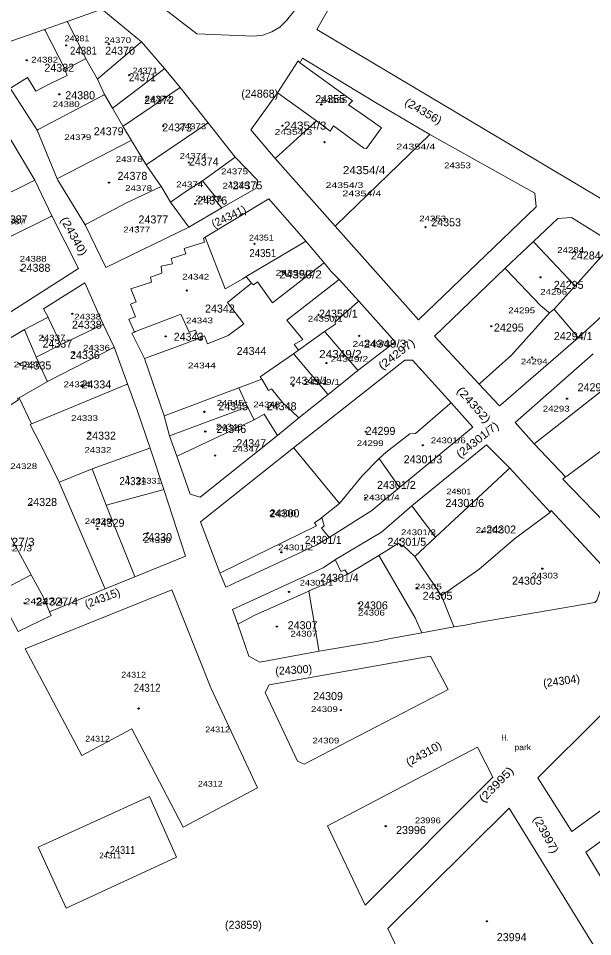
# Model space of a CAD drawing. Extents: x 649608 to 651081, y 237980 to 241202.
# Drawn here: x 650325.9 to 650584.2, y 238660.5 to 239073.7 of the extents above; entities that cross this region are included whole.
import ezdxf

# ---------------------------------------------------------------- set-up
doc = ezdxf.new("R2010")
doc.units = 0
doc.header["$PDMODE"] = 32
doc.header["$PDSIZE"] = 0.5
for name, color, linetype in [('19', 7, 'Continuous'), ('20', 7, 'Continuous'), ('6', 7, 'Continuous')]:
    doc.layers.add(name, color=color, linetype=linetype)
doc.layers.add('3', color=7, linetype='Continuous', lineweight=13)
doc.layers.add('5', color=7, linetype='Continuous', lineweight=13)

msp = doc.modelspace()

# ---------------------------------------------------------------- linework, layer by layer
at = {"layer": '3'}
for p, q in [((650333.268, 239000.784), (650309.651, 239040.458)), ((650433.511, 239000.829), (650423.374, 239011.159)), ((650333.268, 239000.784), (650340.965, 238984.736)), ((650549.32, 238891.838), (650584.458, 238922.778))]:
    msp.add_line(p, q, dxfattribs=at)
for points in [[(650634.917, 238992.051), (650633.914, 238992.9), (650730.416, 239151.667), (650574.402, 239245.255), (650564.003, 239226.917), (650562.503, 239225.238), (650535.575, 239197.674), (650472.242, 239088.563), (650471.65, 239089.049), (650460.092, 239068.577)], [(650450.824, 239078.036), (650446.42, 239072.723), (650443.555, 239069.71), (650439.954, 239067.534), (650435.893, 239066.089), (650431.679, 239065.666), (650406.177, 239066.662), (650387.929, 239080.729), (650389.909, 239083.539), (650386.225, 239086.383), (650392.442, 239094.932), (650393.624, 239097.016), (650398.749, 239100.87)], [(650381.221, 239063.049), (650363.393, 239077.851), (650347.856, 239072.254), (650337.653, 239068.717)], [(650337.653, 239068.717), (650315.85, 239061.08), (650313.77, 239056.136), (650322.253, 239042.174), (650334.272, 239023.41), (650343.346, 239001.41), (650344.344, 239002.082)], [(650634.917, 238992.051), (650623.091, 238971.671), (650460.092, 239068.577)], [(650423.374, 239011.159), (650411.304, 239026.695), (650398.664, 239042.617), (650391.687, 239051.029), (650381.221, 239063.049)], [(650510.99, 239021.351), (650486.457, 239035.738), (650453.649, 239055.761), (650452.467, 239053.677)], [(650452.467, 239053.677), (650451.809, 239054.587), (650442.408, 239040.175)], [(650442.408, 239040.175), (650430.436, 239023.514), (650441.41, 239010.562)], [(650340.965, 238984.736), (650352.967, 238961.072), (650313.65, 238936.034), (650300.262, 238964.625), (650292.437, 238980.621), (650272.393, 239018.949)], [(650510.99, 239021.351), (650558.173, 238995.05), (650558.781, 238988.827), (650505.81, 238938.013), (650468.373, 238980.177), (650441.41, 239010.562)], [(650343.346, 239001.41), (650343.65, 239000.91), (650355.883, 238980.811)], [(650417.428, 238988.393), (650432.862, 238997.289), (650433.511, 239000.829)], [(650455.189, 238973.453), (650438.513, 238992.491), (650409.892, 238975.257)], [(650355.883, 238980.811), (650365.303, 238961.605), (650402.554, 238979.756), (650417.428, 238988.393)], [(650557.608, 238973.197), (650568.5, 238983.626), (650574.654, 238984.056)], [(650574.654, 238984.056), (650593.391, 238972.409), (650612.065, 238961.343)], [(650409.892, 238975.257), (650409.196, 238974.66), (650409.619, 238973.021), (650400.498, 238970.082), (650401.26, 238967.697), (650394.687, 238965.595), (650395.169, 238963.165), (650390.138, 238962.177), (650390.479, 238959.037), (650385.279, 238957.237), (650385.814, 238954.882), (650376.54, 238951.895), (650378.853, 238946.141), (650376.276, 238945.126), (650378.513, 238939.373), (650375.557, 238938.34), (650378.121, 238932.504), (650376.872, 238932.047)], [(650470.107, 238956.158), (650466.615, 238959.822), (650463.479, 238963.693), (650455.189, 238973.453)], [(650533.153, 238909.068), (650513.076, 238930.587), (650544.868, 238961.181), (650557.608, 238973.197)], [(650542.337, 238899.294), (650542.837, 238899.726), (650577.732, 238929.883), (650612.065, 238961.343)], [(650478.527, 238915.245), (650495.37, 238928.17), (650478.959, 238946.38), (650470.107, 238956.158)], [(650339.242, 238939.231), (650337.18, 238943.014), (650355.801, 238954.65), (650364.015, 238936.01), (650369.04, 238925.679), (650375.006, 238909.155)], [(650271.291, 238897.715), (650294.729, 238912.715), (650314.262, 238925.069), (650328.6, 238933.699), (650339.242, 238939.231)], [(650403.125, 238859.534), (650397.127, 238876.638), (650393.802, 238885.779), (650391.423, 238894.805), (650382.565, 238920.602), (650376.872, 238932.047)], [(650449.671, 238880.424), (650499.784, 238919.85), (650500.06, 238919.874)], [(650500.06, 238919.874), (650503.131, 238919.892), (650520.526, 238900.585)], [(650403.125, 238859.534), (650407.586, 238858.228), (650442.453, 238885.884), (650451.993, 238893.975), (650465.186, 238904.357), (650478.527, 238915.245)], [(650375.006, 238909.155), (650379.441, 238896.85), (650385.126, 238880.246), (650391.346, 238861.707)], [(650542.337, 238899.294), (650541.867, 238899.794), (650533.153, 238909.068)], [(650520.526, 238900.585), (650530.259, 238889.734), (650497.303, 238862.53)], [(650598.293, 238837.737), (650570.749, 238866.326), (650572.041, 238867.352), (650557.942, 238882.26), (650549.32, 238891.838)], [(650502.918, 238854.251), (650536.432, 238881.789), (650546.878, 238871.199), (650565.07, 238851.397)], [(650416.54, 238824.133), (650407.867, 238847.157), (650449.671, 238880.424)], [(650391.346, 238861.707), (650401.019, 238831.658), (650378.334, 238822.368), (650364.904, 238817.003), (650339.956, 238806.625), (650340.606, 238804.956)], [(650497.303, 238862.53), (650484.876, 238852.208), (650465.698, 238840.087)], [(650468.522, 238830.107), (650489.204, 238842.525), (650502.918, 238854.251)], [(650565.07, 238851.397), (650565.558, 238852.244), (650590.075, 238825.617), (650590.507, 238824.487), (650586.122, 238811.692), (650585.113, 238810.756), (650533.547, 238801.962), (650526.843, 238800.541), (650521.843, 238799.848), (650507.309, 238797.143)], [(650465.698, 238840.087), (650459.784, 238836.683), (650419.169, 238817.784), (650416.54, 238824.133)], [(650424.676, 238801.128), (650422.174, 238807.605), (650463.019, 238826.481), (650468.522, 238830.107)], [(650340.606, 238804.956), (650325.826, 238797.694), (650318.278, 238811.853), (650316.195, 238815.232)], [(650461.18, 238788.846), (650434.533, 238783.971), (650429.494, 238786.658), (650424.676, 238801.128)], [(650507.309, 238797.143), (650493.309, 238794.621), (650487.193, 238793.233), (650461.18, 238788.846)], [(650591.619, 238681.099), (650581.197, 238698.525), (650599.518, 238711.797), (650621.459, 238728.065)]]:
    msp.add_lwpolyline(points, dxfattribs=at)
for points in [[(650394.908, 238816.572), (650328.88, 238789.988), (650354.501, 238742.001), (650376.901, 238753.911), (650400, 238709.701), (650433.501, 238727.35), (650416.523, 238763.665), (650412.488, 238772.343)], [(650644.085, 238758.04), (650574.778, 238707.779), (650559.577, 238731.881), (650614.901, 238786.963), (650625.096, 238784.845)], [(650519.178, 238771.662), (650454.432, 238738.081), (650451.428, 238739.381), (650436.94, 238770.253), (650438.637, 238773.831), (650511.211, 238786.723)], [(650481.944, 238674.679), (650539.283, 238732.283), (650532.434, 238745.693), (650464.872, 238710.261)], [(650397.039, 238696.218), (650347.348, 238673.27), (650334.766, 238700.71), (650384.944, 238723.488)], [(650594.152, 238641.02), (650591.238, 238636.62), (650514.199, 238616.533), (650509.905, 238625.434), (650505.659, 238623.615), (650491.621, 238653.156), (650496.299, 238655.283), (650492.007, 238664.059), (650546.626, 238718.198)]]:
    msp.add_lwpolyline(points, close=True, dxfattribs=at)
at = {"layer": '5'}
for p, q in [((650408.75, 239000.497), (650423.374, 239011.159)), ((650425.007, 238907.461), (650435.337, 238911.324)), ((650326.272, 238902.97), (650331.8, 238891.132)), ((650470.351, 238855.432), (650462.452, 238849.026))]:
    msp.add_line(p, q, dxfattribs=at)
for points in [[(650347.856, 239072.254), (650348.111, 239071.754), (650353.222, 239061.744), (650356.247, 239055.487), (650361.47, 239046.347), (650364.704, 239039.34), (650368.234, 239033.196), (650372.904, 239025.161), (650376.756, 239018.736), (650383.394, 239007.725)], [(650337.653, 239068.717), (650337.907, 239068.217), (650346.566, 239051.19), (650346.82, 239050.69)], [(650361.47, 239046.347), (650361.97, 239046.77), (650380.721, 239062.626), (650381.221, 239063.049)], [(650346.82, 239050.69), (650355.747, 239055.233), (650356.247, 239055.487)], [(650459.96, 239027.591), (650466.17, 239022.973), (650467.658, 239025.249), (650481.318, 239015.24), (650482.475, 239015.163), (650489.287, 239024.394), (650482.082, 239029.506), (650474.377, 239034.78), (650476.155, 239036.527), (650452.967, 239053.315), (650452.467, 239053.677)], [(650322.253, 239042.174), (650322.753, 239042.485), (650330.07, 239047.034), (650333.777, 239040.91), (650340.098, 239044.215), (650347.89, 239047.982), (650346.82, 239050.69)], [(650368.234, 239033.196), (650368.734, 239033.576), (650391.187, 239050.649), (650391.687, 239051.029)], [(650334.272, 239023.41), (650334.772, 239023.672), (650364.204, 239039.078), (650364.704, 239039.34)], [(650372.904, 239025.161), (650373.404, 239025.5), (650398.164, 239042.278), (650398.664, 239042.617)], [(650442.408, 239040.175), (650442.908, 239039.817), (650459.96, 239027.591)], [(650383.394, 239007.725), (650410.804, 239026.355), (650411.304, 239026.695)], [(650441.41, 239010.562), (650459.46, 239027.132), (650459.96, 239027.591)], [(650344.344, 239002.082), (650376.256, 239018.479), (650376.756, 239018.736)], [(650468.373, 238980.177), (650468.873, 238980.66), (650510.99, 239021.351)], [(650355.883, 238980.811), (650356.383, 238981.074), (650374.271, 238990.501), (650390.18, 238997.991), (650383.394, 239007.725)], [(650292.437, 238980.621), (650292.937, 238980.868), (650333.268, 239000.784)], [(650390.18, 238997.991), (650390.473, 238997.491), (650394.325, 238990.929)], [(650394.325, 238990.929), (650394.825, 238991.28), (650401.633, 238996.063), (650408.75, 239000.497)], [(650417.428, 238988.393), (650417.007, 238988.893), (650413.62, 238992.911), (650414.354, 238993.475), (650408.75, 239000.497)], [(650394.325, 238990.929), (650402.186, 238980.256), (650402.554, 238979.756)], [(650300.262, 238964.625), (650300.762, 238964.872), (650340.465, 238984.489), (650340.965, 238984.736)], [(650409.892, 238975.257), (650410.086, 238974.757), (650418.922, 238951.96), (650426.792, 238956.473), (650428.312, 238957.551)], [(650428.312, 238957.551), (650454.689, 238973.157), (650455.189, 238973.453)], [(650557.608, 238973.197), (650558.079, 238972.697), (650575.866, 238953.826), (650576.337, 238953.326)], [(650576.337, 238953.326), (650592.944, 238971.909), (650593.391, 238972.409)], [(650440.23, 238945.592), (650462.979, 238963.304), (650463.479, 238963.693)], [(650544.868, 238961.181), (650545.344, 238960.681), (650560.801, 238944.454), (650564.326, 238941.516), (650564.826, 238941.099)], [(650428.312, 238957.551), (650428.711, 238957.051), (650430.325, 238955.029), (650430.724, 238954.529)], [(650446.631, 238937.827), (650469.607, 238955.768), (650470.107, 238956.158)], [(650406.914, 238929.711), (650409.636, 238930.729), (650410.955, 238927.163), (650420.213, 238930.937), (650427.256, 238936.146), (650419.888, 238945.816), (650430.724, 238954.529)], [(650430.724, 238954.529), (650431.575, 238953.783), (650433.426, 238955.042), (650440.23, 238945.592)], [(650533.153, 238909.068), (650533.653, 238909.519), (650547.669, 238922.166), (650564.826, 238941.099), (650566.825, 238942.864), (650576.337, 238953.326)], [(650463.631, 238932.767), (650468.499, 238936.108), (650468.209, 238936.911), (650478.459, 238945.94), (650478.959, 238946.38)], [(650378.121, 238932.504), (650378.621, 238932.698), (650397.417, 238939.985), (650398.945, 238940.483), (650402.692, 238932.433), (650405.568, 238933.427), (650406.914, 238929.711)], [(650566.825, 238942.864), (650567.245, 238942.364), (650577.312, 238930.383), (650577.732, 238929.883)], [(650339.242, 238939.231), (650339.479, 238938.731), (650344.891, 238927.337), (650345.128, 238926.837)], [(650345.128, 238926.837), (650363.515, 238935.767), (650364.015, 238936.01)], [(650446.631, 238937.827), (650453.785, 238929.087), (650450.002, 238926.946), (650451.537, 238924.821), (650451.898, 238924.321)], [(650333.956, 238921.229), (650328.815, 238933.199), (650328.6, 238933.699)], [(650435.337, 238911.324), (650434.61, 238912.298), (650449.668, 238922.729), (650451.898, 238924.321), (650463.631, 238932.767)], [(650463.631, 238932.767), (650464.056, 238932.267), (650478.102, 238915.745), (650478.527, 238915.245)], [(650382.565, 238920.602), (650383.065, 238920.785), (650398.214, 238926.322), (650406.414, 238929.516), (650406.914, 238929.711)], [(650333.956, 238921.229), (650334.456, 238921.48), (650345.128, 238926.837)], [(650338.939, 238910.192), (650368.54, 238925.422), (650369.04, 238925.679)], [(650338.939, 238910.192), (650338.713, 238910.692), (650333.956, 238921.229)], [(650449.668, 238922.729), (650450.09, 238922.229), (650464.764, 238904.857), (650465.186, 238904.357)], [(650557.942, 238882.26), (650558.442, 238882.651), (650594.814, 238911.127), (650602.054, 238916.969)], [(650435.337, 238911.324), (650435.629, 238910.824), (650438.334, 238906.19), (650439.68, 238906.938), (650444.864, 238900.621), (650451.493, 238894.441), (650451.993, 238893.975)], [(650306.875, 238889.861), (650325.951, 238901.956), (650325.431, 238902.757), (650326.272, 238902.97), (650338.939, 238910.192)], [(650331.8, 238891.132), (650332.3, 238891.341), (650374.506, 238908.946), (650375.006, 238909.155)], [(650425.007, 238907.461), (650391.923, 238894.993), (650391.423, 238894.805)], [(650393.802, 238885.779), (650394.302, 238885.965), (650428.939, 238898.883), (650425.007, 238907.461)], [(650428.939, 238898.883), (650429.188, 238898.383), (650431.646, 238893.441), (650431.895, 238892.941)], [(650488.133, 238875.584), (650491.268, 238878.448), (650501.904, 238886.755), (650504.585, 238886.915), (650520.026, 238900.156), (650520.526, 238900.585)], [(650572.041, 238867.352), (650572.541, 238867.721), (650614.758, 238898.915)], [(650431.895, 238892.941), (650436.515, 238895.597), (650442.147, 238886.384), (650442.453, 238885.884)], [(650331.8, 238891.132), (650331.164, 238890.846), (650337.751, 238878.114), (650344.265, 238864.977)], [(650397.127, 238876.638), (650397.627, 238876.872), (650431.895, 238892.941)], [(650300.258, 238885.338), (650300.479, 238884.838), (650303.643, 238877.687), (650309.235, 238864.715), (650317.019, 238850.08), (650331.613, 238823.271)], [(650385.126, 238880.246), (650384.626, 238880.067), (650359.093, 238870.94)], [(650470.351, 238855.432), (650450.085, 238879.924), (650449.671, 238880.424)], [(650470.351, 238855.432), (650480.557, 238867.795), (650488.133, 238875.584)], [(650488.133, 238875.584), (650488.484, 238875.084), (650496.952, 238863.03), (650497.303, 238862.53)], [(650359.093, 238870.94), (650344.765, 238865.178), (650344.265, 238864.977)], [(650359.093, 238870.94), (650359.286, 238870.44), (650365.389, 238854.647)], [(650513.557, 238840.232), (650543.313, 238867.925), (650546.378, 238870.74), (650546.878, 238871.199)], [(650344.265, 238864.977), (650364.689, 238817.503), (650364.904, 238817.003)], [(650365.389, 238854.647), (650390.846, 238861.571), (650391.346, 238861.707)], [(650365.389, 238854.647), (650378.133, 238822.868), (650378.334, 238822.368)], [(650502.918, 238854.251), (650503.297, 238853.751), (650513.557, 238840.232)], [(650462.452, 238849.026), (650461.952, 238848.662), (650459.107, 238846.588), (650459.965, 238845.312), (650417.04, 238824.377), (650416.54, 238824.133)], [(650462.452, 238849.026), (650463.389, 238845.355), (650462.302, 238844.282), (650465.293, 238840.587), (650465.698, 238840.087)], [(650516.212, 238813.879), (650516.712, 238814.229), (650532.993, 238825.617), (650548.982, 238839.49), (650564.57, 238851.027), (650565.07, 238851.397)], [(650504.254, 238831.539), (650499.063, 238836.292), (650498.148, 238835.851), (650496.8, 238837.575), (650487.997, 238831.991), (650474.143, 238823.518)], [(650521.843, 238799.848), (650521.642, 238800.348), (650516.212, 238813.879), (650504.254, 238831.539), (650513.557, 238840.232)], [(650468.522, 238830.107), (650468.749, 238829.607), (650470.961, 238824.739), (650472.791, 238825.544), (650474.143, 238823.518)], [(650487.997, 238831.991), (650488.287, 238831.491), (650504.292, 238803.941), (650507.309, 238797.143)], [(650316.195, 238815.232), (650316.695, 238815.493), (650331.113, 238823.01), (650331.613, 238823.271)], [(650331.613, 238823.271), (650337.106, 238813.359), (650339.744, 238807.125), (650339.956, 238806.625)], [(650456.522, 238815.956), (650457.022, 238816.171), (650474.143, 238823.518)], [(650456.522, 238815.956), (650432.473, 238805.236), (650425.176, 238801.391), (650424.676, 238801.128)], [(650461.18, 238788.846), (650461.094, 238789.346), (650456.522, 238815.956)]]:
    msp.add_lwpolyline(points, dxfattribs=at)
at = {"layer": '6'}
for p in [(650347.345, 239061.472), (650366.569, 239062.099), (650329.649, 239054.813), (650375.716, 239048.122), (650344.327, 239039.448), (650383.334, 239038.095), (650462.137, 239034.875), (650390.99, 239025.171), (650444.653, 239025.368), (650355.649, 239020.375), (650463.536, 239017.969), (650402.574, 239008.812), (650366.64, 238999.773), (650421.322, 238999.776), (650405.442, 238990.126), (650379.451, 238979.798), (650509.03, 238979.682), (650432.091, 238972.225), (650575.962, 238968.691), (650327.068, 238960.385), (650444.882, 238959.522), (650560.722, 238957.148), (650401.706, 238951.21), (650350.174, 238940.743), (650460.853, 238940.239), (650538.601, 238935.124), (650336.804, 238930.23), (650392.117, 238930.542), (650407.956, 238929.249), (650479.141, 238930.812), (650350.857, 238923.101), (650557.005, 238921.079), (650326.499, 238918.228), (650464.447, 238918.562), (650354.507, 238908.405), (650449.442, 238908.352), (650572.635, 238902.519), (650438.053, 238898.604), (650409.556, 238896.62), (650357.955, 238887.066), (650409.981, 238887.76), (650482.164, 238887.662), (650507.801, 238881.557), (650414.427, 238876.912), (650374.932, 238867.446), (650523.513, 238861.01), (650481.993, 238857.835), (650331.577, 238854.797), (650440.382, 238852.278), (650361.486, 238843.971), (650384.062, 238842.037), (650534.569, 238842.539), (650497.627, 238838.884), (650444.145, 238833.405), (650561.584, 238826.046), (650447.636, 238815.617), (650505.176, 238817.359), (650328.666, 238810.482), (650479.001, 238810.418), (650442.167, 238799.963), (650379.994, 238763.136), (650470.974, 238762.402), (650491.098, 238710.186), (650365.958, 238698.379), (650536.636, 238667.365)]:
    msp.add_point(p, dxfattribs=at)

# ---------------------------------------------------------------- texts
at = {"layer": '19'}
for s, width, p in [('24381', 0.9, (650349.13, 239057.311)), ('24371', 0.9, (650375.636, 239045.366)), ('24354/3', 1.1, (650445.319, 239023.609)), ('24354/4', 1.1, (650471.825, 239003.558)), ('24351', 0.9, (650429.797, 238966.247)), ('24350/2', 1.1, (650443.215, 238956.632)), ('24349/3', 1.1, (650481.231, 238925.49)), ('24349/2', 1.1, (650461.138, 238920.797)), ('24331', 0.9, (650371.36, 238863.631)), ('24301/1', 0.95, (650454.724, 238837.181)), ('24327/3', 1.1, (650314.073, 238836.328)), ('24327/4', 1.1, (650333.651, 238809.451)), ('24312', 0.9, (650377.772, 238770.63)), ('24311', 0.85, (650367.085, 238697.68))]:
    msp.add_text(s, height=3.6, dxfattribs=dict(at, width=width)).set_placement(p)
for s, p in [('24370', (650364.947, 239057.311)), ('24382', (650337.587, 239049.632)), ('24380', (650346.992, 239037.26)), ('24372', (650382.476, 239035.127)), ('(24868)', (650426.174, 239037.981)), ('24355', (650459.427, 239035.554)), ('24373', (650390.599, 239022.755)), ('24379', (650359.819, 239021.049)), ('24374', (650402.568, 239007.397)), ('24378', (650370.506, 239000.998)), ('24375', (650422.234, 238996.732)), ('24376', (650406.417, 238989.906)), ('24387', (650316.64, 238981.374)), ('24377', (650379.912, 238981.374)), ('24353', (650511.583, 238980.095)), ('24284', (650574.429, 238965.164)), ('24388', (650326.899, 238959.617)), ('24295', (650566.734, 238951.94)), ('24342', (650409.837, 238941.274)), ('24350/1', (650461.125, 238938.992)), ('24338', (650349.985, 238934.021)), ('24295', (650539.8, 238932.742)), ('24343', (650395.751, 238928.588)), ('24294/1', (650566.734, 238928.903)), ('24337', (650336.733, 238925.489)), ('24336', (650349.131, 238920.37)), ('24344', (650424.089, 238922.212)), ('24335', (650327.327, 238915.677)), ('24334', (650354.26, 238907.145)), ('24349/1', (650447.885, 238908.852)), ('24293', (650577.422, 238905.866)), ('24345', (650415.822, 238897.333)), ('24348', (650437.625, 238897.333)), ('24346', (650414.967, 238887.094)), ('24332', (650356.397, 238884.108)), ('24299', (650482.086, 238886.241)), ('24347', (650423.944, 238880.695)), ('24301/3', (650499.185, 238873.443)), ('24301/2', (650487.215, 238861.924)), ('24328', (650329.891, 238854.245)), ('24301/6', (650517.997, 238853.819)), ('24300', (650438.907, 238849.126)), ('24329', (650360.245, 238844.86)), ('24302', (650536.379, 238841.874)), ('24330', (650381.62, 238838.461)), ('24301/5', (650491.918, 238836.328)), ('24301/4', (650461.565, 238820.117)), ('24303', (650547.922, 238818.837)), ('24305', (650507.736, 238812.011)), ('24306', (650478.665, 238807.745)), ('24307', (650447.029, 238798.786)), ('24309', (650458.485, 238766.894)), ('23996', (650495.766, 238706.638)), ('(23859)', (650418.815, 238663.977)), ('23994', (650541.083, 238658.432))]:
    msp.add_text(s, height=3.6, dxfattribs=at).set_placement(p)
for s, rotation, width, p in [('(24356)', 329.796, 1.1, (650499.25, 239034.917)), ('(24340)', 299.268, 1.15, (650344.665, 238983.131)), ('(24297)', 37.797, 1.15, (650489.529, 238915.333)), ('(24352)', 311.695, 1.2, (650522.792, 238905.996)), ('(24301/7)', 38.601, 1.1, (650524.622, 238875.538)), ('(24310)', 29.115, 1.05, (650501.459, 238736.965)), ('(23995)', 46.064, 1.2, (650535.168, 238720.5)), ('(23997)', 298.547, 1.1, (650557.292, 238713.571))]:
    msp.add_text(s, height=3.6, rotation=rotation, dxfattribs=dict(at, width=width)).set_placement(p)
for s, rotation, p in [('(24341)', 25.878, (650413.829, 238979.292)), ('(24315)', 20.854, (650356.552, 238808.175)), ('(24300)', 3.594, (650441.559, 238778.174)), ('(24304)', 7.734, (650562.182, 238772.668))]:
    msp.add_text(s, height=3.6, rotation=rotation, dxfattribs=at).set_placement(p)
at = {"layer": '20'}
for s, width, p in [('24381', 1.15, (650346.714, 239063.363)), ('24370', 1.25, (650364.518, 239062.553)), ('24382', 1.25, (650331.684, 239053.767)), ('24371', 1.15, (650377.332, 239048.886)), ('24372', 1.25, (650382.661, 239036.309)), ('24380', 1.25, (650341.365, 239033.742)), ('24355', 1.25, (650461.705, 239035.529)), ('24373', 1.25, (650398.285, 239023.791)), ('24354/3', 1.35, (650441.109, 239021.271)), ('24379', 1.25, (650346.567, 239018.912)), ('24354/4', 1.4, (650495.871, 239014.659)), ('24378', 1.25, (650369.69, 239009.025)), ('24374', 1.25, (650398.414, 239010.487)), ('24375', 1.25, (650417.088, 239003.508)), ('24353', 1.25, (650517.355, 239006.207)), ('24378', 1.25, (650373.933, 238995.991)), ('24374', 1.25, (650396.905, 238997.651)), ('24375', 1.25, (650417.708, 238997.051)), ('24354/3', 1.35, (650464.086, 238997.302)), ('24376', 1.25, (650405.473, 238991.314)), ('24354/4', 1.4, (650471.609, 238993.57)), ('24387', 1.25, (650316.692, 238980.939)), ('24353', 1.25, (650506.199, 238982.284)), ('24377', 1.25, (650373.111, 238977.313)), ('24351', 1.15, (650429.609, 238973.694)), ('24284', 1.25, (650568.278, 238968.132)), ('24388', 1.25, (650326.503, 238964.169)), ('24350/2', 1.35, (650441.601, 238957.881)), ('24342', 1.25, (650399.628, 238956.099)), ('24296', 1.25, (650560.624, 238949.292)), ('24338', 1.25, (650351.02, 238938.157)), ('24350/1', 1.25, (650456.079, 238937.208)), ('24295', 1.25, (650546.238, 238940.989)), ('24343', 1.25, (650401.316, 238936.421)), ('24337', 1.25, (650334.96, 238928.676)), ('24349/3', 1.35, (650476.146, 238925.854)), ('24336', 1.25, (650354.979, 238924.142)), ('24335', 1.25, (650323.827, 238916.61)), ('24349/2', 1.35, (650466.287, 238919.105)), ('24294', 1.25, (650551.872, 238917.924)), ('24344', 1.3, (650402.148, 238916.16)), ('24349/1', 1.3, (650454.193, 238908.734)), ('24334', 1.25, (650346.237, 238907.69)), ('24345', 1.25, (650415.066, 238899.324)), ('24348', 1.25, (650431.525, 238898.62)), ('24293', 1.25, (650561.761, 238896.732)), ('24333', 1.25, (650349.612, 238892.496)), ('24346', 1.25, (650414.752, 238888.597)), ('24299', 1.25, (650478.08, 238881.199)), ('24301/6', 1.25, (650511.389, 238882.479)), ('24332', 1.25, (650355.634, 238878.161)), ('24347', 1.25, (650422.087, 238878.652)), ('24328', 1.25, (650322.262, 238870.863)), ('24331', 1.15, (650379.08, 238864.282)), ('24301', 1.15, (650518.466, 238859.468)), ('24301/4', 1.3, (650481.066, 238856.795)), ('24329', 1.25, (650355.723, 238846.131)), ('24300', 1.25, (650438.695, 238849.652)), ('24302', 1.25, (650531.647, 238842.146)), ('24301/3', 1.25, (650497.967, 238841.123)), ('24327/3', 1.35, (650315.131, 238833.86)), ('24330', 1.25, (650382.366, 238837.554)), ('24301/2', 1.25, (650442.698, 238834.293)), ('24303', 1.25, (650556.603, 238821.619)), ('24301/1', 1.2, (650452.436, 238818.389)), ('24305', 1.25, (650504.217, 238816.698)), ('24327/4', 1.4, (650328.554, 238810.011)), ('24306', 1.25, (650478.631, 238804.933)), ('24307', 1.25, (650448.266, 238795.462)), ('24312', 1.15, (650372.191, 238777.023)), ('24309', 1.25, (650457.494, 238761.521)), ('24312', 1.15, (650409.958, 238752.403)), ('24312', 1.15, (650355.971, 238748.223)), ('24309', 1.25, (650458.161, 238747.39)), ('H.', 0.85, (650543.114, 238748.71)), ('park', 1.1, (650549.027, 238744.37)), ('24312', 1.15, (650406.669, 238727.93)), ('23996', 1.2, (650504.277, 238711.472))]:
    msp.add_text(s, height=2.6, dxfattribs=dict(at, width=width)).set_placement(p)
msp.add_text('24311', height=2.6, dxfattribs=at).set_placement((650362.344, 238695.675))

doc.saveas('drawing.dxf')
